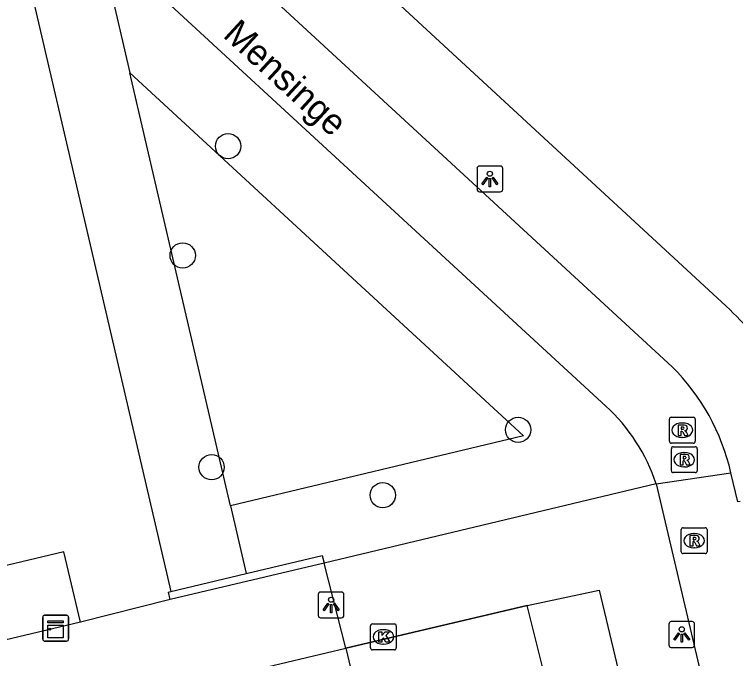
# Model space of a CAD drawing. Extents: x 158038 to 159242, y 380133 to 381214.
# Drawn here: x 158702.78 to 158730.68, y 380633.11 to 380658.03 of the extents above; entities that cross this region are included whole.
import ezdxf

# ---------------------------------------------------------------- set-up
doc = ezdxf.new("R2010")
doc.units = 0
for name, color, linetype in [('IMGEO_Boom', 7, 'Continuous'), ('IMGEO_Fietspad_open', 7, 'Continuous'), ('IMGEO_Groenvoorziening', 7, 'Continuous'), ('IMGEO_Hek', 7, 'Continuous'), ('IMGEO_Kast', 7, 'Continuous'), ('IMGEO_Kolk', 7, 'Continuous'), ('IMGEO_Lichtpunt', 7, 'Continuous'), ('IMGEO_Muur', 7, 'Continuous'), ('IMGEO_Openbare_ruimte_label', 7, 'Continuous'), ('IMGEO_Pand', 7, 'Continuous'), ('IMGEO_Rioolput', 7, 'Continuous'), ('IMGEO_Voetpad_open', 7, 'Continuous')]:
    doc.layers.add(name, color=color, linetype=linetype)

msp = doc.modelspace()

# ---------------------------------------------------------------- linework, layer by layer
at = {"layer": 'IMGEO_Boom'}
for centre in [(158711.047, 380652.931), (158709.29, 380648.704), (158722.268, 380641.96), (158710.409, 380640.513), (158717.032, 380639.431)]:
    msp.add_circle(centre, 0.489, dxfattribs=at)
at = {"layer": 'IMGEO_Fietspad_open'}
for points in [[(158728.229, 380644.402), (158704.073, 380666.661)], [(158706.04, 380660.954), (158725.661, 380642.88)], [(158727.607, 380639.865), (158730.507, 380640.298)], [(158730.863, 380639.184), (158730.767, 380639.169), (158730.507, 380640.298)], [(158727.607, 380639.865), (158741.77, 380579.626), (158742.026, 380578.534)]]:
    msp.add_lwpolyline(points, dxfattribs=at)
for centre, radius, start, end in [((158722.253, 380638.401), 8.469, 12.9444, 45.1221), ((158720.969, 380637.716), 6.977, 17.9375, 47.7421)]:
    msp.add_arc(centre, radius, start, end, dxfattribs=at)
at = {"layer": 'IMGEO_Groenvoorziening'}
for points in [[(158706.04, 380660.954), (158707.246, 380655.764)], [(158703.146, 380660.152), (158708.827, 380635.706)], [(158707.246, 380655.764), (158722.483, 380641.728), (158711.136, 380639.023)], [(158711.136, 380639.023), (158707.246, 380655.764)], [(158711.136, 380639.023), (158711.747, 380636.397)]]:
    msp.add_lwpolyline(points, dxfattribs=at)
at = {"layer": 'IMGEO_Hek'}
for points in [[(158708.805, 380635.392), (158705.341, 380634.52)], [(158722.624, 380635.163), (158715.598, 380633.518)]]:
    msp.add_lwpolyline(points, dxfattribs=at)
at = {"layer": 'IMGEO_Kast'}
for p, q in [((158703.948, 380634.787), (158704.789, 380634.787)), ((158704.789, 380634.787), (158703.948, 380634.787)), ((158703.873, 380633.862), (158703.873, 380634.703)), ((158703.873, 380634.703), (158703.873, 380633.862)), ((158704.873, 380634.712), (158704.873, 380633.871)), ((158704.873, 380633.871), (158704.873, 380634.712)), ((158704.798, 380633.787), (158703.957, 380633.787)), ((158703.957, 380633.787), (158704.798, 380633.787))]:
    msp.add_line(p, q, dxfattribs=at)
for points in [[(158704.068, 380634.577), (158704.668, 380634.577), (158704.668, 380634.492), (158704.068, 380634.492), (158704.068, 380634.577)], [(158704.068, 380634.402), (158704.668, 380634.402), (158704.668, 380633.913), (158704.068, 380633.913), (158704.068, 380634.402)]]:
    msp.add_lwpolyline(points, dxfattribs=at)
msp.add_circle((158704.152, 380634.251), 0.0377, dxfattribs=at)
for centre, start, end in [((158703.951, 380634.709), 92.4484, 184.2845), ((158703.951, 380634.709), 92.4484, 184.2845), ((158704.795, 380634.709), 2.4484, 94.2845), ((158704.795, 380634.709), 2.4484, 94.2845), ((158703.951, 380633.865), 182.4484, 274.2845), ((158703.951, 380633.865), 182.4484, 274.2845), ((158704.795, 380633.865), 272.4484, 4.2845), ((158704.795, 380633.865), 272.4484, 4.2845)]:
    msp.add_arc(centre, 0.0779, start, end, dxfattribs=at)
at = {"layer": 'IMGEO_Kolk'}
for p, q in [((158716.555, 380633.525), (158716.555, 380634.377)), ((158716.63, 380634.451), (158717.482, 380634.451)), ((158717.043, 380634.231), (158717.068, 380634.231)), ((158717.556, 380634.377), (158717.556, 380633.525)), ((158717.066, 380633.671), (158717.041, 380633.671)), ((158717.482, 380633.451), (158716.63, 380633.451))]:
    msp.add_line(p, q, dxfattribs=at)
for points in [[(158716.555, 380633.525), (158716.555, 380634.377)], [(158716.63, 380634.451), (158717.482, 380634.451)], [(158717.556, 380634.377), (158717.556, 380633.525)], [(158716.876, 380634.151), (158716.999, 380634.151), (158716.999, 380634), (158717.129, 380634.151), (158717.293, 380634.151), (158717.147, 380634), (158717.3, 380633.751), (158717.148, 380633.751), (158717.063, 380633.915), (158716.999, 380633.848), (158716.999, 380633.751), (158716.876, 380633.751), (158716.876, 380634.151)], [(158717.482, 380633.451), (158716.63, 380633.451)]]:
    msp.add_lwpolyline(points, dxfattribs=at)
for centre, start, end in [((158716.632, 380634.375), 91.552, 178.448), ((158716.632, 380634.375), 91.552, 178.448), ((158717.48, 380634.375), 1.552, 88.448), ((158717.48, 380634.375), 1.552, 88.448), ((158716.632, 380633.527), 181.552, 268.448), ((158716.632, 380633.527), 181.552, 268.448), ((158717.48, 380633.527), 271.552, 358.448), ((158717.48, 380633.527), 271.552, 358.448)]:
    msp.add_arc(centre, 0.0765, start, end, dxfattribs=at)
for centre, major_axis, ratio, start_param, end_param in [((158717.042, 380633.951), (-0.387, 0.002), 0.722429, 4.712389, 7.853982), ((158717.067, 380633.951), (-0.39, 0.002), 0.717154, 1.570796, 4.712389)]:
    msp.add_ellipse(centre, major_axis=major_axis, ratio=ratio, start_param=start_param, end_param=end_param, dxfattribs=at)
at = {"layer": 'IMGEO_Lichtpunt'}
for p, q in [((158721.581, 380652.162), (158720.773, 380652.162)), ((158721.581, 380652.162), (158720.773, 380652.162)), ((158720.679, 380652.067), (158720.679, 380651.26)), ((158720.679, 380652.067), (158720.679, 380651.26)), ((158721.675, 380651.26), (158721.675, 380652.067)), ((158721.675, 380651.26), (158721.675, 380652.067)), ((158720.773, 380651.166), (158721.581, 380651.166)), ((158720.773, 380651.166), (158721.581, 380651.166)), ((158715.436, 380635.686), (158714.628, 380635.686)), ((158715.436, 380635.686), (158714.628, 380635.686)), ((158714.534, 380635.591), (158714.534, 380634.784)), ((158714.534, 380635.591), (158714.534, 380634.784)), ((158715.53, 380634.784), (158715.53, 380635.591)), ((158715.53, 380634.784), (158715.53, 380635.591)), ((158714.628, 380634.69), (158715.436, 380634.69)), ((158714.628, 380634.69), (158715.436, 380634.69)), ((158729.005, 380634.542), (158728.197, 380634.542)), ((158729.005, 380634.542), (158728.197, 380634.542)), ((158728.103, 380634.447), (158728.103, 380633.64)), ((158728.103, 380634.447), (158728.103, 380633.64)), ((158729.099, 380633.64), (158729.099, 380634.447)), ((158729.099, 380633.64), (158729.099, 380634.447)), ((158728.197, 380633.546), (158729.005, 380633.546)), ((158728.197, 380633.546), (158729.005, 380633.546))]:
    msp.add_line(p, q, dxfattribs=at)
for points in [[(158721.053, 380651.731), (158721.092, 380651.703), (158720.904, 380651.441), (158720.866, 380651.468), (158721.053, 380651.731)], [(158721.155, 380651.683), (158721.202, 380651.683), (158721.202, 380651.361), (158721.155, 380651.361), (158721.155, 380651.683)], [(158721.265, 380651.703), (158721.303, 380651.73), (158721.49, 380651.468), (158721.451, 380651.44), (158721.265, 380651.703)], [(158714.908, 380635.255), (158714.947, 380635.227), (158714.759, 380634.965), (158714.721, 380634.992), (158714.908, 380635.255)], [(158715.01, 380635.207), (158715.057, 380635.207), (158715.057, 380634.885), (158715.01, 380634.885), (158715.01, 380635.207)], [(158715.12, 380635.227), (158715.158, 380635.254), (158715.345, 380634.992), (158715.306, 380634.964), (158715.12, 380635.227)], [(158728.477, 380634.111), (158728.516, 380634.083), (158728.328, 380633.821), (158728.29, 380633.848), (158728.477, 380634.111)], [(158728.579, 380634.063), (158728.626, 380634.063), (158728.626, 380633.741), (158728.579, 380633.741), (158728.579, 380634.063)], [(158728.689, 380634.083), (158728.727, 380634.11), (158728.914, 380633.848), (158728.875, 380633.82), (158728.689, 380634.083)]]:
    msp.add_lwpolyline(points, dxfattribs=at)
for centre in [(158721.178, 380651.865), (158715.033, 380635.389), (158728.602, 380634.245)]:
    msp.add_circle(centre, 0.0994, dxfattribs=at)
for centre, start, end in [((158720.773, 380652.067), 90, 180), ((158720.773, 380652.067), 90, 180), ((158721.581, 380652.067), 0, 90), ((158721.581, 380652.067), 0, 90), ((158720.773, 380651.26), 180, 270), ((158720.773, 380651.26), 180, 270), ((158721.581, 380651.26), 270, 0), ((158721.581, 380651.26), 270, 360), ((158714.628, 380635.591), 90, 180), ((158714.628, 380635.591), 90, 180), ((158715.436, 380635.591), 0, 90), ((158715.436, 380635.591), 0, 90), ((158714.628, 380634.784), 180, 270), ((158714.628, 380634.784), 180, 270), ((158715.436, 380634.784), 270, 0), ((158715.436, 380634.784), 270, 360), ((158728.197, 380634.447), 90, 180), ((158728.197, 380634.447), 90, 180), ((158729.005, 380634.447), 0, 90), ((158729.005, 380634.447), 0, 90), ((158728.197, 380633.64), 180, 270), ((158728.197, 380633.64), 180, 270), ((158729.005, 380633.64), 270, 0), ((158729.005, 380633.64), 270, 360)]:
    msp.add_arc(centre, 0.0946, start, end, dxfattribs=at)
at = {"layer": 'IMGEO_Muur'}
for points in [[(158711.747, 380636.397), (158714.693, 380637.095), (158714.762, 380636.803)], [(158714.762, 380636.803), (158708.805, 380635.392)], [(158708.827, 380635.706), (158711.747, 380636.397)], [(158708.805, 380635.392), (158708.736, 380635.684), (158708.827, 380635.706)]]:
    msp.add_lwpolyline(points, dxfattribs=at)
at = {"layer": 'IMGEO_Pand'}
for points in [[(158705.341, 380634.52), (158704.695, 380637.244), (158700.391, 380636.223), (158701.037, 380633.499)], [(158722.624, 380635.163), (158725.401, 380635.761), (158726.416, 380631.538)], [(158726.416, 380631.538), (158723.693, 380630.884), (158722.624, 380635.163)], [(158705.341, 380634.52), (158701.037, 380633.499)], [(158709.509, 380632.073), (158715.598, 380633.518)], [(158715.598, 380633.518), (158716.938, 380627.87)]]:
    msp.add_lwpolyline(points, dxfattribs=at)
at = {"layer": 'IMGEO_Rioolput'}
for p, q in [((158728.123, 380641.518), (158728.123, 380642.37)), ((158728.198, 380642.444), (158729.05, 380642.444)), ((158729.124, 380642.37), (158729.124, 380641.518)), ((158728.611, 380642.224), (158728.636, 380642.224)), ((158728.634, 380641.664), (158728.609, 380641.664)), ((158729.05, 380641.444), (158728.198, 380641.444)), ((158728.199, 380640.379), (158728.199, 380641.231)), ((158728.274, 380641.305), (158729.126, 380641.305)), ((158729.2, 380641.231), (158729.2, 380640.379)), ((158728.687, 380641.085), (158728.712, 380641.085)), ((158728.71, 380640.525), (158728.685, 380640.525)), ((158729.126, 380640.305), (158728.274, 380640.305)), ((158728.658, 380638.173), (158729.51, 380638.173)), ((158728.583, 380637.247), (158728.583, 380638.099)), ((158729.071, 380637.953), (158729.096, 380637.953)), ((158729.584, 380638.099), (158729.584, 380637.247)), ((158729.094, 380637.393), (158729.069, 380637.393)), ((158729.51, 380637.173), (158728.658, 380637.173))]:
    msp.add_line(p, q, dxfattribs=at)
for points in [[(158728.123, 380641.518), (158728.123, 380642.37)], [(158728.198, 380642.444), (158729.05, 380642.444)], [(158729.124, 380642.37), (158729.124, 380641.518)], [(158728.712, 380642.142), (158728.46, 380642.144), (158728.46, 380641.744)], [(158728.638, 380642.063), (158728.584, 380642.063), (158728.584, 380641.982)], [(158728.46, 380641.744), (158728.584, 380641.744), (158728.584, 380641.906), (158728.595, 380641.906)], [(158728.584, 380641.982), (158728.636, 380641.982)], [(158728.642, 380641.877), (158728.713, 380641.744), (158728.853, 380641.744), (158728.788, 380641.87)], [(158729.05, 380641.444), (158728.198, 380641.444)], [(158728.199, 380640.379), (158728.199, 380641.231)], [(158728.274, 380641.305), (158729.126, 380641.305)], [(158729.2, 380641.231), (158729.2, 380640.379)], [(158728.788, 380641.003), (158728.536, 380641.005), (158728.536, 380640.605)], [(158728.714, 380640.924), (158728.66, 380640.924), (158728.66, 380640.843)], [(158728.536, 380640.605), (158728.66, 380640.605), (158728.66, 380640.767), (158728.671, 380640.767)], [(158728.66, 380640.843), (158728.712, 380640.843)], [(158728.718, 380640.738), (158728.789, 380640.605), (158728.929, 380640.605), (158728.864, 380640.731)], [(158729.126, 380640.305), (158728.274, 380640.305)], [(158728.658, 380638.173), (158729.51, 380638.173)], [(158728.583, 380637.247), (158728.583, 380638.099)], [(158729.172, 380637.871), (158728.92, 380637.873), (158728.92, 380637.473)], [(158729.584, 380638.099), (158729.584, 380637.247)], [(158728.92, 380637.473), (158729.044, 380637.473), (158729.044, 380637.635), (158729.055, 380637.635)], [(158729.098, 380637.792), (158729.044, 380637.792), (158729.044, 380637.711)], [(158729.044, 380637.711), (158729.096, 380637.711)], [(158729.102, 380637.606), (158729.173, 380637.473), (158729.313, 380637.473), (158729.248, 380637.599)], [(158729.51, 380637.173), (158728.658, 380637.173)]]:
    msp.add_lwpolyline(points, dxfattribs=at)
for centre, radius, start, end in [((158728.2, 380642.368), 0.0765, 91.552, 178.448), ((158728.2, 380642.368), 0.0765, 91.552, 178.448), ((158729.048, 380642.368), 0.0765, 1.552, 88.448), ((158729.048, 380642.368), 0.0765, 1.552, 88.448), ((158728.644, 380641.967), 0.0964, 77.0061, 93.1865), ((158728.658, 380642.024), 0.0378, 276.6634, 79.6772), ((158728.711, 380642.032), 0.109, 350.3612, 89.416), ((158728.594, 380641.853), 0.0533, 26.0293, 88.6989), ((158728.62, 380642.171), 0.19, 274.7715, 282.9687), ((158728.709, 380642.032), 0.112, 277.5842, 350.9817), ((158728.693, 380641.817), 0.108, 29.5134, 73.7905), ((158728.2, 380641.52), 0.0765, 181.552, 268.448), ((158728.2, 380641.52), 0.0765, 181.552, 268.448), ((158729.048, 380641.52), 0.0765, 271.552, 358.448), ((158729.048, 380641.52), 0.0765, 271.552, 358.448), ((158728.276, 380641.229), 0.0765, 91.552, 178.448), ((158728.276, 380641.229), 0.0765, 91.552, 178.448), ((158729.124, 380641.229), 0.0765, 1.552, 88.448), ((158729.124, 380641.229), 0.0765, 1.552, 88.448), ((158728.72, 380640.828), 0.0964, 77.0061, 93.1865), ((158728.734, 380640.885), 0.0378, 276.6634, 79.6772), ((158728.787, 380640.893), 0.109, 350.3612, 89.416), ((158728.67, 380640.714), 0.0533, 26.0293, 88.6989), ((158728.696, 380641.032), 0.19, 274.7715, 282.9687), ((158728.785, 380640.893), 0.112, 277.5842, 350.9817), ((158728.769, 380640.678), 0.108, 29.5134, 73.7905), ((158728.276, 380640.381), 0.0765, 181.552, 268.448), ((158728.276, 380640.381), 0.0765, 181.552, 268.448), ((158729.124, 380640.381), 0.0765, 271.552, 358.448), ((158729.124, 380640.381), 0.0765, 271.552, 358.448), ((158728.66, 380638.097), 0.0765, 91.552, 178.448), ((158728.66, 380638.097), 0.0765, 91.552, 178.448), ((158729.508, 380638.097), 0.0765, 1.552, 88.448), ((158729.508, 380638.097), 0.0765, 1.552, 88.448), ((158729.171, 380637.761), 0.109, 350.3612, 89.416), ((158729.054, 380637.582), 0.0533, 26.0293, 88.6989), ((158729.08, 380637.9), 0.19, 274.7715, 282.9687), ((158729.104, 380637.696), 0.0964, 77.0061, 93.1865), ((158729.118, 380637.753), 0.0378, 276.6634, 79.6772), ((158729.169, 380637.761), 0.112, 277.5842, 350.9817), ((158729.153, 380637.546), 0.108, 29.5134, 73.7905), ((158728.66, 380637.249), 0.0765, 181.552, 268.448), ((158728.66, 380637.249), 0.0765, 181.552, 268.448), ((158729.508, 380637.249), 0.0765, 271.552, 358.448), ((158729.508, 380637.249), 0.0765, 271.552, 358.448)]:
    msp.add_arc(centre, radius, start, end, dxfattribs=at)
for centre, major_axis, ratio, start_param, end_param in [((158728.61, 380641.944), (-0.387, 0.002), 0.722429, 4.712389, 7.853982), ((158728.635, 380641.944), (-0.39, 0.002), 0.717154, 1.570796, 4.712389), ((158728.686, 380640.805), (-0.387, 0.002), 0.722429, 4.712389, 7.853982), ((158728.711, 380640.805), (-0.39, 0.002), 0.717154, 1.570796, 4.712389), ((158729.07, 380637.673), (-0.387, 0.002), 0.722429, 4.712389, 7.853982), ((158729.095, 380637.673), (-0.39, 0.002), 0.717154, 1.570796, 4.712389)]:
    msp.add_ellipse(centre, major_axis=major_axis, ratio=ratio, start_param=start_param, end_param=end_param, dxfattribs=at)
at = {"layer": 'IMGEO_Voetpad_open'}
for points in [[(158708.828, 380669.343), (158706.466, 380668.758), (158730.316, 380646.742)], [(158727.607, 380639.865), (158714.762, 380636.803)], [(158715.598, 380633.518), (158714.762, 380636.803)], [(158708.805, 380635.392), (158705.341, 380634.52)], [(158715.598, 380633.518), (158722.624, 380635.163)]]:
    msp.add_lwpolyline(points, dxfattribs=at)
msp.add_arc((158723.83, 380639.578), 9.664, 29.5355, 47.8423, dxfattribs=at)

# ---------------------------------------------------------------- texts
at = {"layer": 'IMGEO_Openbare_ruimte_label'}
msp.add_text('Mensinge', height=1, rotation=317.391, dxfattribs=at).set_placement((158710.808, 380657.178))

doc.saveas('drawing.dxf')
